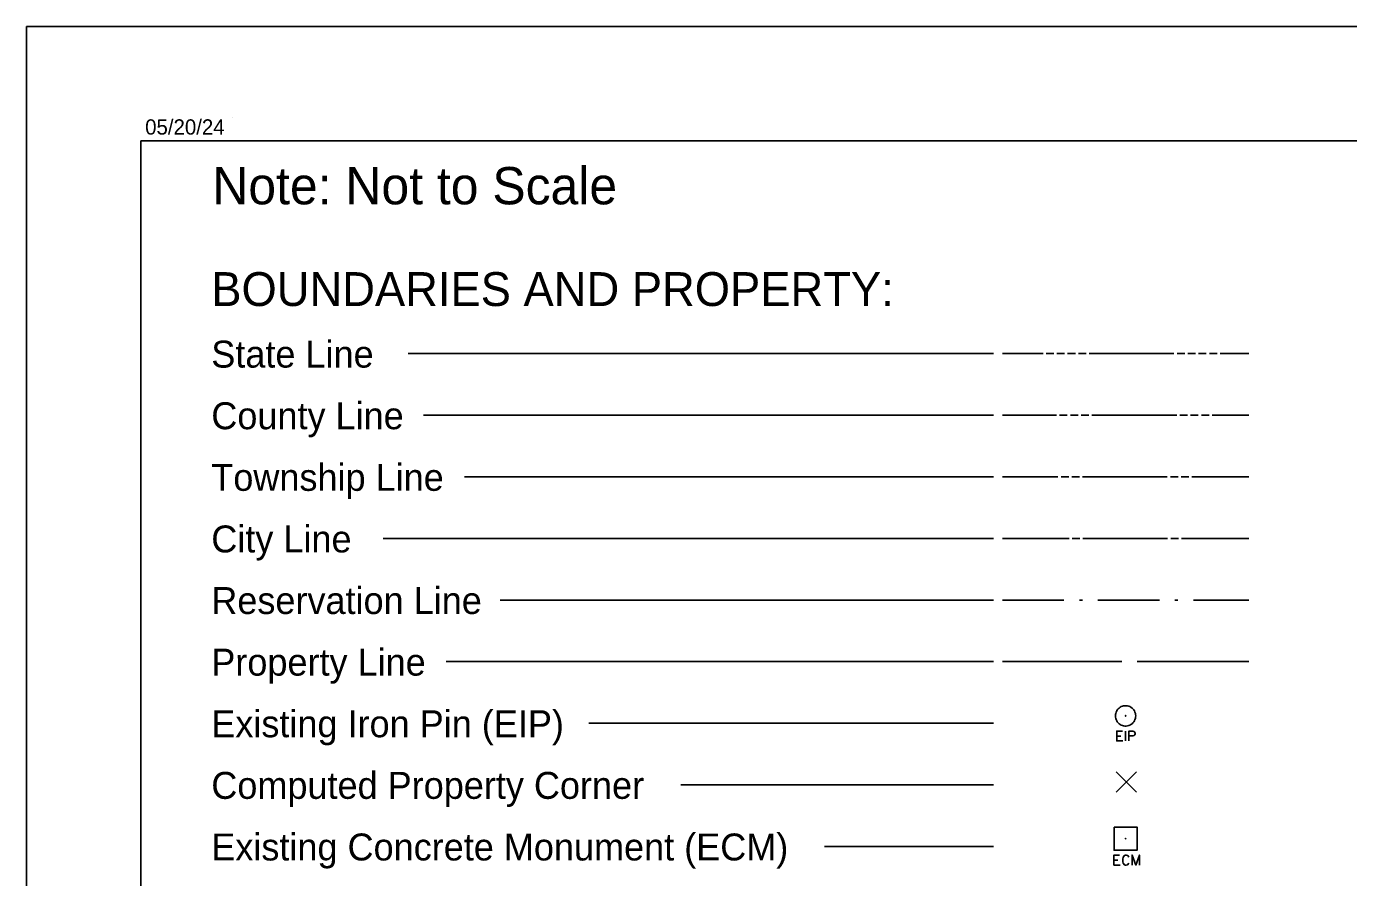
# Model space of a CAD drawing. Extents: x 1855058 to 1858918, y 1540202 to 1542502.
# Drawn here: x 1857118.6 to 1857551.6, y 1542223 to 1542501.8 of the extents above; entities that cross this region are included whole.
import ezdxf

# ---------------------------------------------------------------- set-up
doc = ezdxf.new("R2010")
doc.units = 0
for name, color, linetype in [('Default', 7, 'Continuous'), ('Exist Contamination Potential Cell', 7, 'Continuous'), ('Sheet Data Field CELL', 7, 'Continuous'), ('Sheet Symbology CELL', 7, 'Continuous')]:
    doc.layers.add(name, color=color, linetype=linetype)

msp = doc.modelspace()

# ---------------------------------------------------------------- linework, layer by layer
at = {"layer": 'Default'}
msp.add_lwpolyline([(1857118.6, 1542501.77), (1857118.6, 1541401.77), (1858818.6, 1541401.77), (1858818.6, 1542501.77)], close=True, dxfattribs=at)
at = {"layer": 'Exist Contamination Potential Cell'}
for p, q in [((1858818.6, 1542501.77), (1857118.6, 1542501.77)), ((1857118.6, 1542501.77), (1857118.6, 1541401.77))]:
    msp.add_line(p, q, dxfattribs=at)
at = {"layer": 'Sheet Data Field CELL'}
for p, q in [((1857435.28, 1542394.6), (1857243.6, 1542394.6)), ((1857438.18, 1542394.6), (1857451.5, 1542394.6)), ((1857452.51, 1542394.6), (1857455.03, 1542394.6)), ((1857456.04, 1542394.6), (1857458.56, 1542394.6)), ((1857459.57, 1542394.6), (1857462.1, 1542394.6)), ((1857463.1, 1542394.6), (1857465.63, 1542394.6)), ((1857466.64, 1542394.6), (1857494.38, 1542394.6)), ((1857495.39, 1542394.6), (1857497.91, 1542394.6)), ((1857498.92, 1542394.6), (1857501.44, 1542394.6)), ((1857502.45, 1542394.6), (1857504.98, 1542394.6)), ((1857505.98, 1542394.6), (1857508.51, 1542394.6)), ((1857509.52, 1542394.6), (1857518.9, 1542394.6)), ((1857435.28, 1542374.42), (1857248.63, 1542374.42)), ((1857438.18, 1542374.42), (1857455.93, 1542374.42)), ((1857456.94, 1542374.42), (1857459.46, 1542374.42)), ((1857460.47, 1542374.42), (1857462.99, 1542374.42)), ((1857464, 1542374.42), (1857466.52, 1542374.42)), ((1857467.53, 1542374.42), (1857495.28, 1542374.42)), ((1857496.29, 1542374.42), (1857498.81, 1542374.42)), ((1857499.82, 1542374.42), (1857502.34, 1542374.42)), ((1857503.35, 1542374.42), (1857505.87, 1542374.42)), ((1857506.88, 1542374.42), (1857518.9, 1542374.42)), ((1857435.28, 1542354.24), (1857262.05, 1542354.24)), ((1857438.18, 1542354.24), (1857456.39, 1542354.24)), ((1857457.4, 1542354.24), (1857459.93, 1542354.24)), ((1857460.94, 1542354.24), (1857463.46, 1542354.24)), ((1857464.47, 1542354.24), (1857492.21, 1542354.24)), ((1857493.22, 1542354.24), (1857495.74, 1542354.24)), ((1857496.75, 1542354.24), (1857499.27, 1542354.24)), ((1857500.28, 1542354.24), (1857518.9, 1542354.24)), ((1857435.28, 1542334.06), (1857235.44, 1542334.06)), ((1857438.18, 1542334.06), (1857460.01, 1542334.06)), ((1857461.02, 1542334.06), (1857463.55, 1542334.06)), ((1857464.55, 1542334.06), (1857492.3, 1542334.06)), ((1857493.31, 1542334.06), (1857495.83, 1542334.06)), ((1857496.84, 1542334.06), (1857518.9, 1542334.06)), ((1857435.28, 1542313.88), (1857273.78, 1542313.88)), ((1857438.18, 1542313.88), (1857458.36, 1542313.88)), ((1857463.41, 1542313.88), (1857464.42, 1542313.88)), ((1857469.46, 1542313.88), (1857489.64, 1542313.88)), ((1857494.68, 1542313.88), (1857495.69, 1542313.88)), ((1857500.74, 1542313.88), (1857518.9, 1542313.88)), ((1857435.28, 1542293.71), (1857256.03, 1542293.71)), ((1857438.18, 1542293.71), (1857477.28, 1542293.71)), ((1857482.32, 1542293.71), (1857518.9, 1542293.71)), ((1857435.28, 1542273.53), (1857302.82, 1542273.53)), ((1857478.55, 1542267.73), (1857478.55, 1542270.95)), ((1857475.65, 1542269.35), (1857476.97, 1542269.35)), ((1857435.28, 1542253.35), (1857332.93, 1542253.35)), ((1857482.09, 1542250.91), (1857475.42, 1542257.57)), ((1857475.42, 1542250.91), (1857482.09, 1542257.57)), ((1857435.28, 1542233.17), (1857379.97, 1542233.17)), ((1857474.73, 1542228.73), (1857476.05, 1542228.73))]:
    msp.add_line(p, q, dxfattribs=at)
for points in [[(1857481.87, 1542275.95), (1857481.84, 1542276.38), (1857481.76, 1542276.78), (1857481.62, 1542277.18), (1857481.46, 1542277.56), (1857481.22, 1542277.91), (1857480.95, 1542278.23), (1857480.66, 1542278.52), (1857480.31, 1542278.76), (1857479.96, 1542278.98), (1857479.56, 1542279.11), (1857479.16, 1542279.22), (1857478.76, 1542279.27), (1857478.33, 1542279.27), (1857477.9, 1542279.22), (1857477.5, 1542279.11), (1857477.12, 1542278.98), (1857476.74, 1542278.76), (1857476.4, 1542278.52), (1857476.1, 1542278.23), (1857475.83, 1542277.91), (1857475.62, 1542277.56), (1857475.43, 1542277.18), (1857475.3, 1542276.78), (1857475.22, 1542276.38), (1857475.19, 1542275.95), (1857475.22, 1542275.52), (1857475.3, 1542275.12), (1857475.43, 1542274.71), (1857475.62, 1542274.34), (1857475.83, 1542273.99), (1857476.1, 1542273.67), (1857476.4, 1542273.37), (1857476.74, 1542273.13), (1857477.12, 1542272.92), (1857477.5, 1542272.78), (1857477.9, 1542272.68), (1857478.33, 1542272.62), (1857478.76, 1542272.62), (1857479.16, 1542272.68), (1857479.56, 1542272.78), (1857479.96, 1542272.92), (1857480.31, 1542273.13), (1857480.66, 1542273.37), (1857480.95, 1542273.67), (1857481.22, 1542273.99), (1857481.46, 1542274.34), (1857481.62, 1542274.71), (1857481.76, 1542275.12), (1857481.84, 1542275.52), (1857481.87, 1542275.95)], [(1857478.6, 1542276.03), (1857478.51, 1542276.06), (1857478.46, 1542276), (1857478.43, 1542275.92), (1857478.49, 1542275.87), (1857478.57, 1542275.84), (1857478.62, 1542275.89), (1857478.65, 1542275.97), (1857478.6, 1542276.03)], [(1857477.51, 1542270.95), (1857475.65, 1542270.95), (1857475.65, 1542267.73), (1857477.64, 1542267.73)], [(1857479.62, 1542267.73), (1857479.62, 1542270.95), (1857480.92, 1542270.95), (1857481.3, 1542270.83), (1857481.63, 1542270.32), (1857481.63, 1542270.01), (1857481.32, 1542269.5), (1857480.92, 1542269.38), (1857479.62, 1542269.38)], [(1857474.75, 1542239.52), (1857482.31, 1542239.52), (1857482.31, 1542231.96), (1857474.75, 1542231.96), (1857474.75, 1542239.52)], [(1857478.52, 1542235.83), (1857478.48, 1542235.79), (1857478.48, 1542235.72), (1857478.55, 1542235.64), (1857478.63, 1542235.68), (1857478.67, 1542235.75), (1857478.59, 1542235.83), (1857478.52, 1542235.83)], [(1857476.59, 1542230.33), (1857474.73, 1542230.33), (1857474.73, 1542227.1), (1857476.72, 1542227.1)], [(1857479.64, 1542229.7), (1857479.23, 1542230.23), (1857478.83, 1542230.33), (1857478.55, 1542230.33), (1857478.16, 1542230.23), (1857477.73, 1542229.7), (1857477.63, 1542228.98), (1857477.63, 1542228.6), (1857477.63, 1542228.35), (1857477.66, 1542228.12), (1857477.73, 1542227.71), (1857478.16, 1542227.2), (1857478.55, 1542227.1), (1857478.77, 1542227.1), (1857479.21, 1542227.2), (1857479.64, 1542227.71)], [(1857480.68, 1542227.1), (1857480.68, 1542230.33), (1857481.9, 1542227.1), (1857483.07, 1542230.33), (1857483.07, 1542227.1)]]:
    msp.add_lwpolyline(points, dxfattribs=at)
at = {"layer": 'Sheet Symbology CELL'}
for p, q in [((1857186.06, 1542471.8), (1857186.06, 1542471.8)), ((1857156.1, 1541439.27), (1857156.1, 1542464.27)), ((1858781.1, 1542464.27), (1857156.1, 1542464.27))]:
    msp.add_line(p, q, dxfattribs=at)

# ---------------------------------------------------------------- texts
at = {"layer": 'Sheet Data Field CELL'}
for s, height, p in [('Note: Not to Scale', 12.2158, (1857179.47, 1542443.5)), ('BOUNDARIES AND PROPERTY:', 11.0983, (1857179.13, 1542410.19)), ('State Line', 8.828, (1857179.14, 1542390.02)), ('County Line', 8.8282, (1857179.14, 1542369.84)), ('Township Line', 8.8282, (1857179.14, 1542349.66)), ('City Line', 8.828, (1857179.14, 1542329.48)), ('Reservation Line', 8.8282, (1857179.14, 1542309.31)), ('Property Line', 8.8282, (1857179.14, 1542289.13)), ('Existing Iron Pin (EIP)', 8.8282, (1857179.14, 1542268.95)), ('Computed Property Corner', 8.8282, (1857179.14, 1542248.77)), ('Existing Concrete Monument (ECM)', 8.8282, (1857179.14, 1542228.59))]:
    msp.add_text(s, height=height, dxfattribs=at).set_placement(p)
at = {"layer": 'Sheet Symbology CELL'}
msp.add_text('05/20/24', height=5, rotation=0, dxfattribs=at).set_placement((1857157.48, 1542466.34))

doc.saveas('drawing.dxf')
